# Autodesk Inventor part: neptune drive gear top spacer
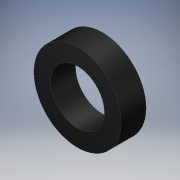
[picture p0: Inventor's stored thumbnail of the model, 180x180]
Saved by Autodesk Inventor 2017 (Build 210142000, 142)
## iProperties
Created: 2016-07
Part Number: neptune drive gear top spacer
Material: Generic
Document SubType Name: Modeling
Designer: Stan
Density: 1 g/cm^3
Appearance: Glossy - Black
Author: Stan
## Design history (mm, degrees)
sketch "Sketch1"
  geometry: C1 r 3.429 at (0, 0); C2 r 5.556 at (0, 0); 1 further point
  constraints: 2 centre point, 2 coincident
  dimensions: "d0" = 6.858 diameter of C1; "d1" = 11.1125 diameter of C2
extrude "Extrusion1" new body sketch "Sketch1" distance "d2" = 3.175; taper "d3" = 0 deg
body "Solid1"
